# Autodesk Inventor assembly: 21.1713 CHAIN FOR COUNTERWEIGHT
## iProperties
Created: 2006-10
Part Number: 21.1713 CHAIN FOR COUNTERWEIGHT
Document SubType Name: Assembly
Designer: Andy Moles
Mass: 4.64418 g
Surface Area: 15.2422 cm^2
Volume: 0.591615 cm^3
Density: 7.85 g/cm^3
Author: Andy Moles
